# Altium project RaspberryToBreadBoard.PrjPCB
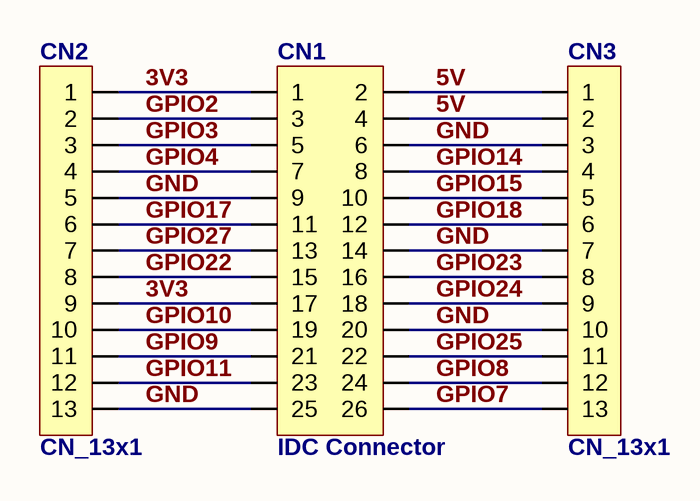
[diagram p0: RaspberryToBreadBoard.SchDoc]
1 sheet, 3 parts. Net scope: global (net labels, ports and power ports of the same name join across sheets).
Board file: RaspberryToBreadBoard.PcbDoc

## Sheet RaspberryToBreadBoard.SchDoc: Raspberry To BreadBoard
size A4; Date: 12-04-2013; CheckedBy: X; DrawnBy: JFK; Revision: 1.0.0; SheetNumber: 1; SheetTotal: 1; Projectnumber: OWN-000; Size: A4

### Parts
CN1  IDC Connector  [IDC26]
CN2  CN_13x1  [GP_13x1]
CN3  CN_13x1  [GP_13x1]

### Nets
3V3: CN1.1 CN1.17 CN2.1 CN2.9
5V: CN1.2 CN1.4 CN3.1 CN3.2
GND: CN1.6 CN1.9 CN1.14 CN1.20 CN1.25 CN2.5 CN2.13 CN3.3 CN3.7 CN3.10
GPIO2: CN1.3 CN2.2
GPIO3: CN1.5 CN2.3
GPIO4: CN1.7 CN2.4
GPIO7: CN1.26 CN3.13
GPIO8: CN1.24 CN3.12
GPIO9: CN1.21 CN2.11
GPIO10: CN1.19 CN2.10
GPIO11: CN1.23 CN2.12
GPIO14: CN1.8 CN3.4
GPIO15: CN1.10 CN3.5
GPIO17: CN1.11 CN2.6
GPIO18: CN1.12 CN3.6
GPIO22: CN1.15 CN2.8
GPIO23: CN1.16 CN3.8
GPIO24: CN1.18 CN3.9
GPIO25: CN1.22 CN3.11
GPIO27: CN1.13 CN2.7

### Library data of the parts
CN1 = CN_13x2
